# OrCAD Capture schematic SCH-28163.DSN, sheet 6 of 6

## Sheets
6 4. I/O Headers and Power Supply: size C
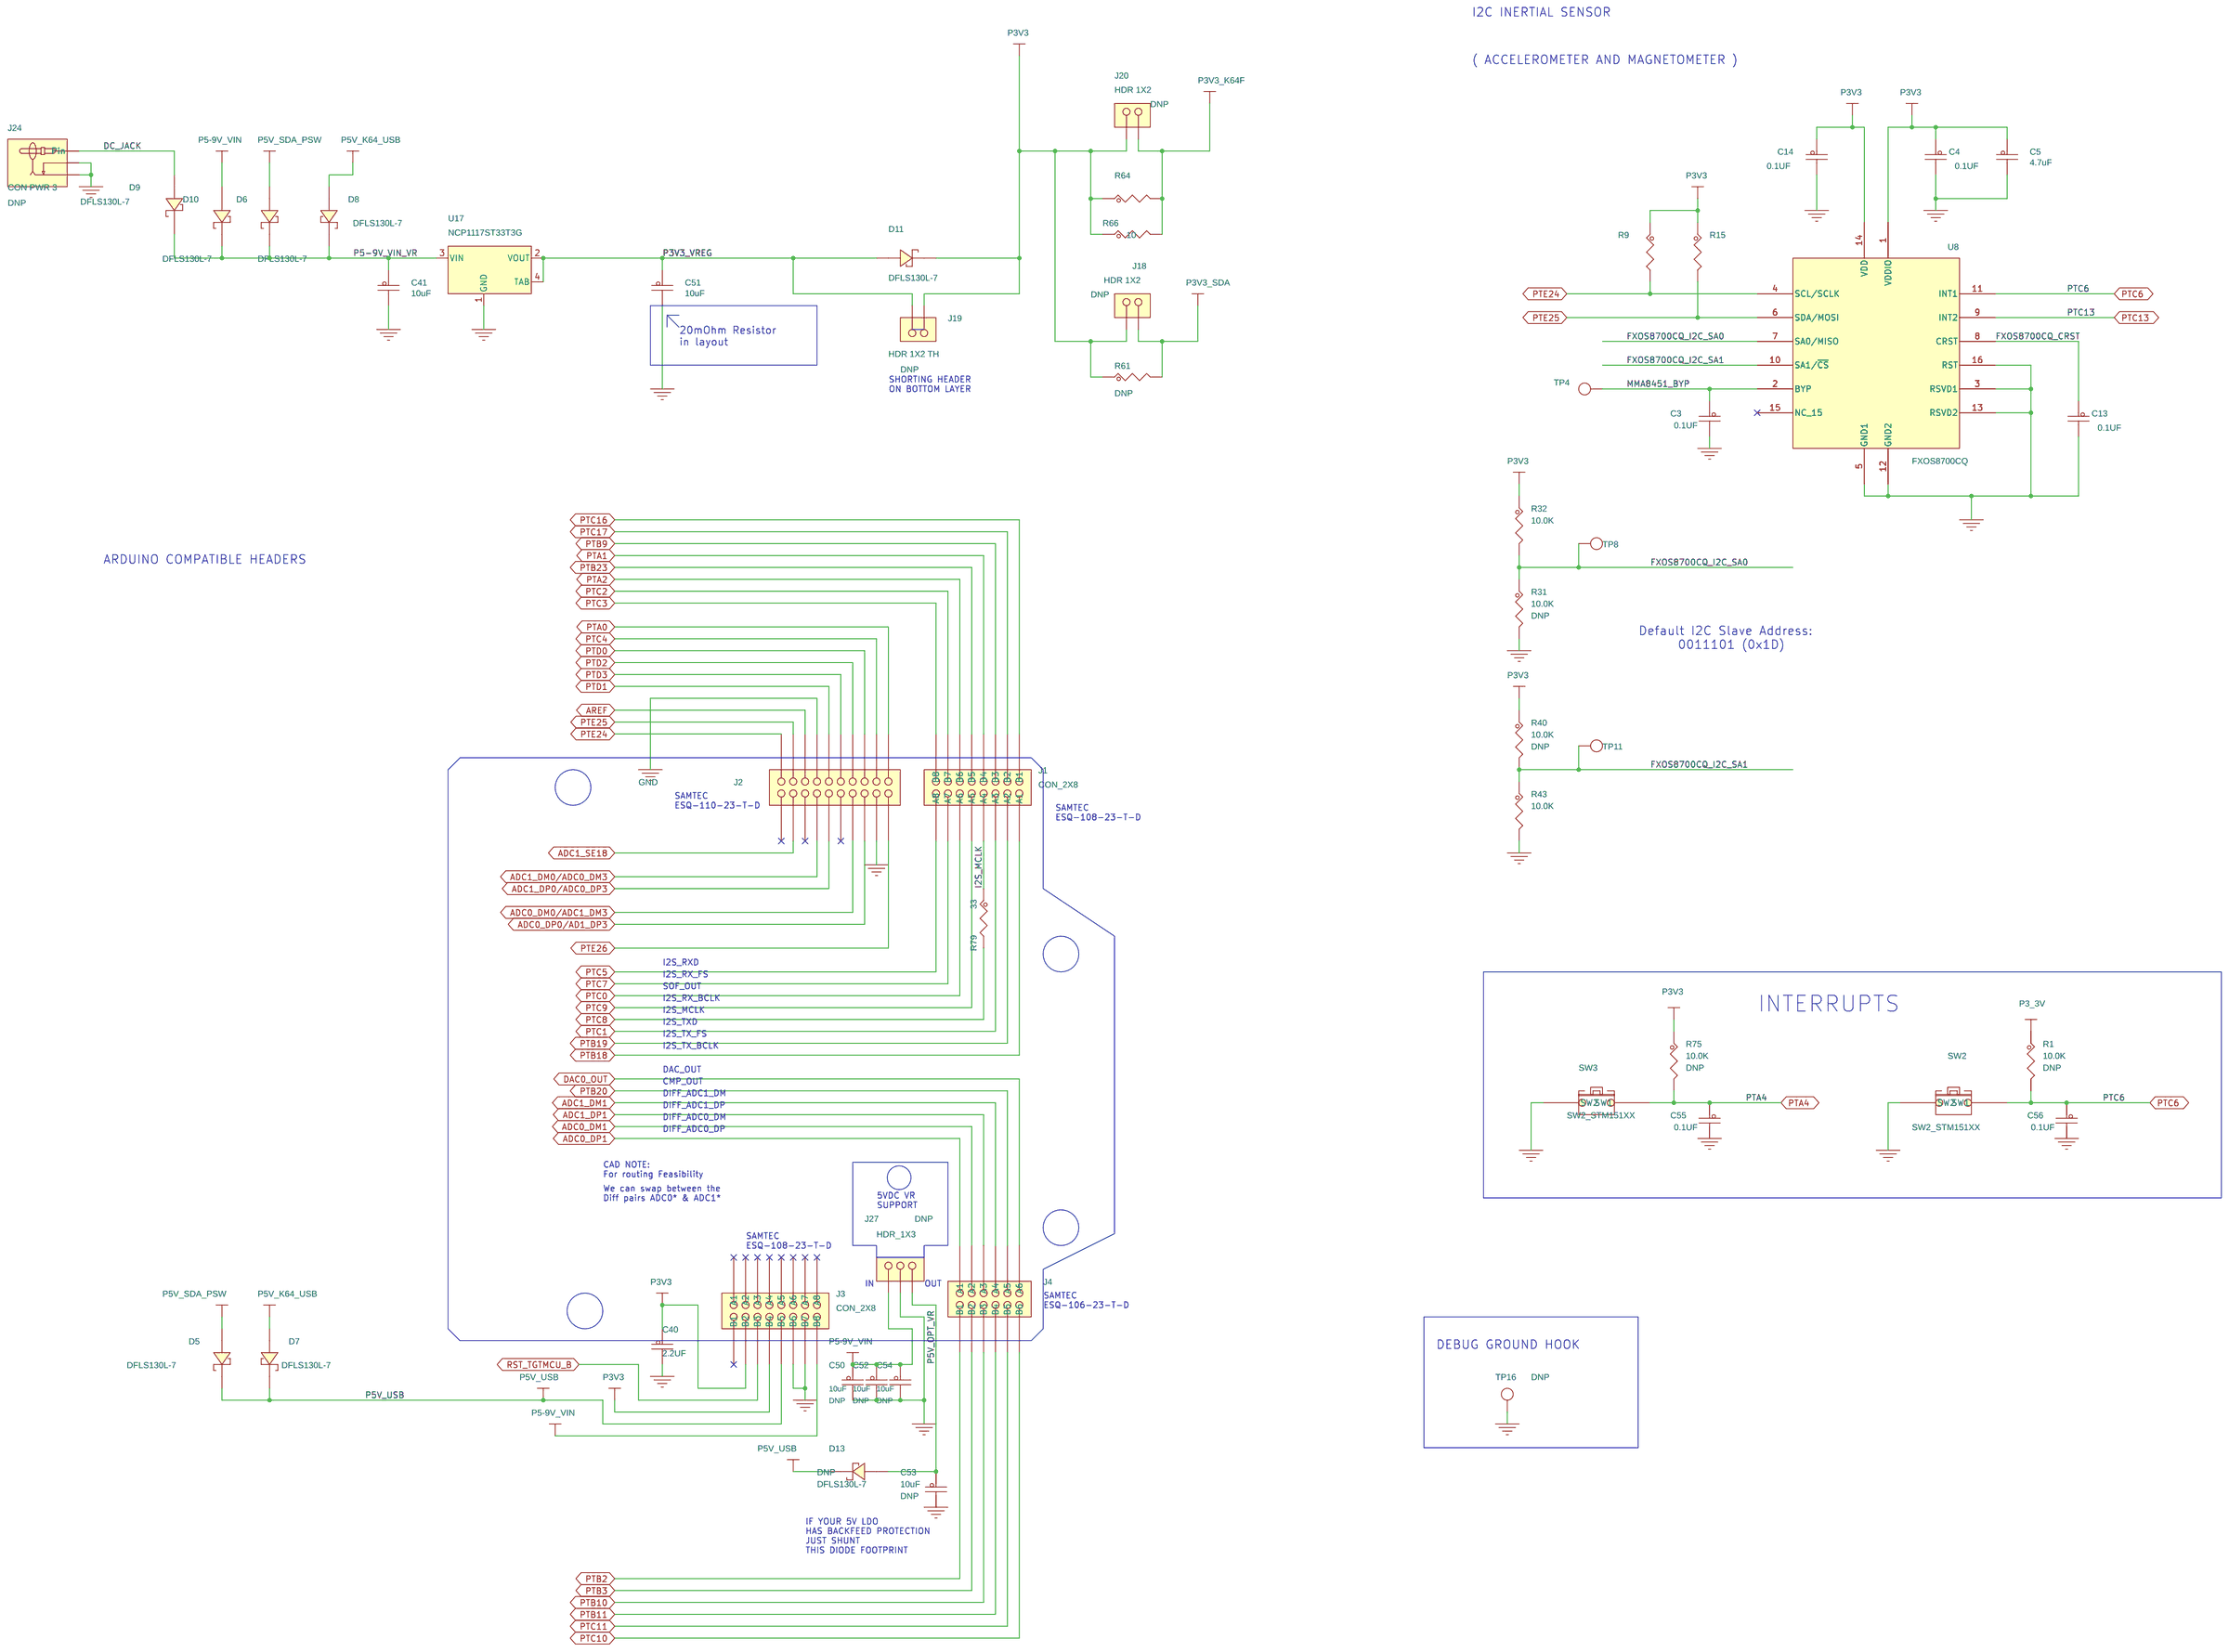
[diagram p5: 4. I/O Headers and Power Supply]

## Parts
C3  0.1UF  [CC0402_25]
C4  0.1UF  [CC0402_25]
C5  4.7uF  [CC0603_OV]
C13  0.1UF  [CC0402_25]
C14  0.1UF  [CC0402_25]
C40  2.2UF  [CC0603_OV]
C41  10uF  [CC0603_OV]
C50  10uF  [CC0603_OV]
C51  10uF  [CC0603_OV]
C52  10uF  [CC0603_OV]
C53  10uF  [CC0603_OV]
C54  10uF  [CC0603_OV]
C55  0.1UF  [CC0402_25]
C56  0.1UF  [CC0402_25]
D5  DFLS130L-7  [powerdi-123_3mmx2mm]
D6  DFLS130L-7  [powerdi-123_3mmx2mm]
D7  DFLS130L-7  [powerdi-123_3mmx2mm]
D8  DFLS130L-7  [powerdi-123_3mmx2mm]
D9  DFLS130L-7  [powerdi-123_3mmx2mm]
D10  DFLS130L-7  [powerdi-123_3mmx2mm]
D11  DFLS130L-7  [powerdi-123_3mmx2mm]
D13  DFLS130L-7  [powerdi-123_3mmx2mm]
J1  CON_2X8  [HDR208_ESQ_SKT]
J2  SKT_2x10  [hdr210_esq_skt]
J3  CON_2X8  [HDR208_ESQ_SKT]
J4  CON_2X6  [HDR206_ESQ_SKT]
J18  HDR 1X2  [hdr102]
J19  HDR 1X2 TH  [SH_HDR102_BOTTOM]
J20  HDR 1X2  [hdr102]
J24  CON PWR 3  [con_jack_pj1_022_th-ra]
J27  HDR_1X3  [HDR103]
R1  10.0K  [RC0402_25]
R9  4.7K  [RC0603_OV]
R15  4.7K  [RC0603_OV]
R31  10.0K  [RC0402_25]
R32  10.0K  [RC0402_25]
R40  10.0K  [RC0402_25]
R43  10.0K  [RC0402_25]
R61  0  [RC0402_25]
R64  0  [RC0402_25]
R66  10  [RC0603_OV]
R75  10.0K  [RC0402_25]
R79  33  [RC0402_25]
SW2  SW2_STM151XX  [sw2_4x3mm_sm]
SW3  SW2_STM151XX  [sw2_4x3mm_sm]
TP4  TPAD_030  [TPAD_030]
TP8  TPAD_030  [TPAD_030]
TP11  TPAD_030  [TPAD_030]
TP16  TEST POINT WHITE  [TEST_LOOP]
U8  FXOS8700CQ  [qfn5x3_0p5_3x3]
U17  NCP1117ST33T3G  [sot223]

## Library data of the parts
C3 C4 C13 C14 C55 C56 = CAP_NP: CAP CER 0.1UF 10V 10% X5R 0402; AGILE_PN: 150-75634; CAD_APPROVED: Yes; FPLIST: CC0402_25,CC0402_HD,0402_CC; HEIGHT: 0.64MM; MFG_NAME01: KEMET; MFG_PN01: C0402C104K8PAC; PRIORITY_PN: 021-00169; ROHS: Yes; SIGNAL_MODEL: DEFAULT_CAPACITOR_100000pF_2_1; Tolerance: 10%; VOLTAGE: 10V
C5 = CAP_NP: CAP CER 4.7uF 16V 10% X5R 0603; AGILE_PN: 150-78976; CAD_APPROVED: Yes; FPLIST: CC0603_OV,CC0603,0603_CC; HEIGHT: 0.9 MM; MFG_NAME01: TDK; MFG_PN01: C1608X5R1C475K; ROHS: Yes; SIGNAL_MODEL: DEFAULT_CAPACITOR_4.7e+06pF_2_1; Tolerance: 10%; VOLTAGE: 16V
C40 = CAP_NP: CAP CER 2.2UF 10V 10% X7R 0603; AGILE_PN: 150-78564; CAD_APPROVED: Yes; FPLIST: CC0603_OV,CC0603,0603_CC; HEIGHT: 1.25MM; MFG_NAME01: TAIYO YUDEN; MFG_PN01: LMK107B7225KA-T; ROHS: Yes; SIGNAL_MODEL: DEFAULT_CAPACITOR_2.2e+06pF_2_1; Tolerance: 10%; VOLTAGE: 10V
C41 = CAP_NP: CAP CER 10uF 16V 20% X5R 0603; AGILE_PN: 150-79092; CAD_APPROVED: Yes; FPLIST: CC0603_OV,CC0603,0603_CC; HEIGHT: 1mm; MFG_NAME01: TAIYO YUDEN; MFG_PN01: EMK107BBJ106MA-T; ROHS: Yes; SIGNAL_MODEL: DEFAULT_CAPACITOR_1e+07pF_2_1; Tolerance: 20%; VOLTAGE: 16V
C50 C52-C54 = CAP_NP: CAP CER 10UF 10V 20% X5R 0603; AGILE_PN: 150-78609; ASSY_OPT: DNP; CAD_APPROVED: Yes; FPLIST: CC0603_OV,CC0603,0603_CC; HEIGHT: 1.016MM; MFG_NAME01: TAIYO YUDEN; MFG_PN01: LMK107BJ106MALTD; ROHS: Yes; SIGNAL_MODEL: DEFAULT_CAPACITOR_1e+07pF_2_1; VOLTAGE: 10V
C51 = CAP_NP: CAP CER 10UF 10V 20% X5R 0603; AGILE_PN: 150-78609; CAD_APPROVED: Yes; FPLIST: CC0603_OV,CC0603,0603_CC; HEIGHT: 1.016MM; MFG_NAME01: TAIYO YUDEN; MFG_PN01: LMK107BJ106MALTD; ROHS: Yes; SIGNAL_MODEL: DEFAULT_CAPACITOR_1e+07pF_2_1; VOLTAGE: 10V
D5-D11 = DIODE_SCHTKY: DIODE SCH 1A 30V PowerDI123; AGILE_PN: 480-78285; CAD_APPROVED: Yes; HEIGHT: 1MM; MFG_NAME01: DIODES INC; ROHS: Yes
D13 = DIODE_SCHTKY: DIODE SCH 1A 30V PowerDI123; AGILE_PN: 480-78285; ASSY_OPT: DNP; CAD_APPROVED: Yes; HEIGHT: 1MM; MFG_NAME01: DIODES INC; ROHS: Yes
J1 J3 = CONN_HDR_8X2: CON 2X8 SKT TH 100MIL CTR 545H SN 190L; AGILE_PN: 210-80538; CAD_APPROVED: Yes; HEIGHT: 13.843MM; MFG_NAME01: samtec; MFG_PN01: ESQ-108-23-T-D; ROHS: Yes
J2 = CONN_HDR_10X2: CON 2X10 SKT TH 100MIL CTR 540H SN 190L; AGILE_PN: 210-80537; CAD_APPROVED: Yes; HEIGHT: 13.72MM; MFG_NAME01: SAMTEC; MFG_PN01: ESQ-110-23-T-D; ROHS: Yes
J4 = CONN_HDR_6X2: CON 2X6 SKT TH 100MIL CTR 540H SN 190L; AGILE_PN: 210-80536; CAD_APPROVED: Yes; HEIGHT: 13.72MM; MFG_NAME01: SAMTEC; MFG_PN01: ESQ-106-23-T-D; ROHS: Yes
J18 J20 = CONN_HDR_2X1: HDR 1X2 TH 100MIL SP 330H SN 115L; AGILE_PN: 210-76752; ASSY_OPT: DNP; CAD_APPROVED: Yes; HEIGHT: 8.58MM; MFG_NAME01: Samtec; MFG_PN01: TSW-102-23-T-S; ROHS: Yes
J19 = CONN_HDR_2X1: HDR 1X2 TH 100MIL SP 339H AU 98L; AGILE_PN: 210-75439; ASSY_OPT: DNP; CAD_APPROVED: YES; FPLIST: HDR102,SH_HDR102_BOTTOM; HEIGHT: 8.71 MM; MFG_NAME01: SAMTEC; MFG_PN01: TSW-102-07-G-S; PRIORITY_PN: 028-00556; ROHS: Yes
J24 = DC_POWER_JACK: CON 3 PWR JACK RA TH --- 201H AG 118L; AGILE_PN: 210-80316; ASSY_OPT: DNP; CAD_APPROVED: Yes; HEIGHT: 5.1MM; MFG_NAME01: CUI Inc; MFG_PN01: PJ1-022; ROHS: Yes
J27 = CONN_HDR_3X1: HDR 1X3 TH 100MIL SP 330H AU 98L; AGILE_PN: 210-75442; ASSY_OPT: DNP; CAD_APPROVED: Yes; HEIGHT: 8.38 MM; MFG_NAME01: SAMTEC; MFG_PN01: HTSW-103-07-S-S; PRIORITY_PN: 028-00700; ROHS: Yes
R1 R75 = RES: RES MF 10.0K 1/16W 1% AEC-Q200 0402; AGILE_PN: 470-75416; ASSY_OPT: DNP; CAD_APPROVED: Yes; FPLIST: RC0402_25,RC0402_HD,0402_CC; HEIGHT: 0.4MM; MFG_NAME01: VISHAY INTERTECHNOLOGY; MFG_PN01: CRCW040210K0FKED; PRIORITY_PN: 006-00552; ROHS: Yes; SIGNAL_MODEL: DEFAULT_RESISTOR_10000OHM_2_1; TOL: 1%; Tolerance: 1%
R9 R15 = RES: RES MF 4.7K 1/10W 5% 0603; AGILE_PN: 470-75414; CAD_APPROVED: Yes; FPLIST: RC0603_OV,RC0603,0603_CC; MFG_NAME01: VISHAY INTERTECHNOLOGY; MFG_PN01: CRCW06034K70JNEA; ROHS: Yes; SIGNAL_MODEL: DEFAULT_RESISTOR_4700OHM_2_1; Tolerance: 5%
R31 R40 = RES: RES MF 10.0K 1/16W 1% AEC-Q200 0402; AGILE_PN: 470-75416; ASSY_OPT: DNP; CAD_APPROVED: Yes; FPLIST: RC0402_25,RC0402_HD,0402_CC; MFG_NAME01: VISHAY INTERTECHNOLOGY; MFG_PN01: CRCW040210K0FKED; PRIORITY_PN: 006-00552; ROHS: Yes; SIGNAL_MODEL: DEFAULT_RESISTOR_10000OHM_2_1; Tolerance: 1%
R32 R43 = RES: RES MF 10.0K 1/16W 1% AEC-Q200 0402; AGILE_PN: 470-75416; CAD_APPROVED: Yes; FPLIST: RC0402_25,RC0402_HD,0402_CC; MFG_NAME01: VISHAY INTERTECHNOLOGY; MFG_PN01: CRCW040210K0FKED; PRIORITY_PN: 006-00552; ROHS: Yes; SIGNAL_MODEL: DEFAULT_RESISTOR_10000OHM_2_1; Tolerance: 1%
R61 = RES: RES MF ZERO OHM 1/16W 5% 0402; AGILE_PN: 470-75394; ASSY_OPT: DNP; CAD_APPROVED: Yes; FPLIST: RC0603_OV,RC0603,R603-X2,0603_CC; MFG_NAME01: ROHM; MFG_PN01: MCR01MZPJ000; PRIORITY_PN: 006-00559; ROHS: Yes; SIGNAL_MODEL: DEFAULT_RESISTOR_0.001OHM_2_1; Tolerance: 5%; VOLTAGE: 1/16W
R64 = RES: RES MF ZERO OHM 1/16W 5% 0402; AGILE_PN: 470-75394; CAD_APPROVED: Yes; FPLIST: RC0603_OV,RC0603,R603-X2,0603_CC; MFG_NAME01: ROHM; MFG_PN01: MCR01MZPJ000; PRIORITY_PN: 006-00559; ROHS: Yes; SIGNAL_MODEL: DEFAULT_RESISTOR_0.001OHM_2_1; Tolerance: 5%; VOLTAGE: 1/16W
R66 = RES: RES MF 10 OHM 1/10W 5% 0603; AGILE_PN: 470-75847; CAD_APPROVED: Yes; FPLIST: RC0603_OV,RC0603,0603_CC; MFG_NAME01: KOA SPEER; MFG_PN01: RK73B1JTTD100J; ROHS: Yes; SIGNAL_MODEL: DEFAULT_RESISTOR_10.000000OHM_2_1; Tolerance: 5%; VOLTAGE: 50V
R79 = RES: RES MF 33.0 OHM 1/16W 1% 0402; AGILE_PN: 470-75790; CAD_APPROVED: Yes; FPLIST: RC0402_25,RC0402_HD,RC0402_X2,0402_CC; MFG_NAME01: THYE MING TECH CO LTD; MFG_PN01: CR-02FL6---33R; ROHS: Yes; Tolerance: 1%
SW2 SW3 = SW2_STM151XX: SW SPST MOM NO TACT 12V 50MA SMT; AGILE_PN: 510-76958; CAD_APPROVED: Yes; HEIGHT: 2MM; MFG_NAME01: E SWITCH; MFG_PN01: TL1015BF160QG; ROHS: Yes
TP4 TP8 TP11 = TestLoop: TEST POINT PAD 30MIL DIA SMT, NO PART TO ORDER; AGILE_PN: 211-76642; CAD_APPROVED: Yes; HEIGHT: 0.1MM; MFG_NAME01: NOTACOMPONENT; MFG_PN01: NOTACOMPONENT; ROHS: Yes
TP16 = TestLoop: TEST POINT WHITE 40 MIL DRILL 180 MIL TH 109L; AGILE_PN: 210-75685; ASSY_OPT: DNP; CAD_APPROVED: Yes; HEIGHT: 4.8 MM; MFG_NAME01: COMPONENTS CORPORATION; MFG_PN01: TP-105-01-09; PRIORITY_PN: 028-00434; ROHS: Yes
U8 = FXOS8700CQ_QFN_16P: IC ACCELEROMETER AND MAGNETOMETER SENSOR 3-AXIS 2.5V QFN16; AGILE_PN: TMP-WF-16648; CAD_APPROVED: Yes; HEIGHT: 1.25MM; MFG_NAME01: Freescale Semiconductor; PRE_APN: 312-80418; ROHS: Yes; VOLTAGE: 2.5V
U17 = LD1117AS18: IC VREG LDO 1A 3.3V SOT223; AGILE_PN: 312-80039; CAD_APPROVED: Yes; HEIGHT: 1.8MM; MFG_NAME01: ON Semiconductor; ROHS: Yes

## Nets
GND: C3.2 C4.2 C5.2 C13.2 C14.2 C40.2 C41.2 C50.2 C51.2 C52.2 C53.2 C54.2 C55.2 C56.2 J2.3 J2.14 J3.12(B6) J3.14(B7) J24.2 J24.3 J27.2 R31.2 R43.2 SW2.2(SW2) SW3.2(SW2) TP16.1(Pin1) U8.3(RSVD1) U8.5(GND1) U8.12(GND2) U8.13(RSVD2) U8.16(RST) U17.1(GND) ; also on sheet 2 3 4 5
P3V3: C4.1 C5.1 C14.1 C40.1 D11.C J3.4(B2) J3.8(B4) J18.2 J19.1 J20.1 R1.1 R9.1 R15.1 R32.1 R40.1 R61.1 R64.1 R66.1 R75.1 U8.1(VDDIO) U8.14(VDD) ; also on sheet 2 3 4 5
P3V3_K64F: J20.2 R64.2 R66.2 ; also on sheet 2
P3V3_SDA: J18.1 R61.2 ; also on sheet 3
P3V3_VREG: C51.1 D11.A J19.2 U17.2(VOUT) U17.4(TAB)
P5V_K64_USB: D7.A D8.A ; also on sheet 2
P5V_OPT_VR: C53.1 D13.A J27.3
P5V_SDA_PSW: D5.A D6.A ; also on sheet 3
P5V_USB: D5.C D7.C D13.C J3.10(B5) ; also on sheet 2
ADC0_DM0/ADC1_DM3: J2.7 ; also on sheet 2
ADC0_DM1: J4.3(A2) ; also on sheet 2
ADC0_DP0/AD1_DP3: J2.5 ; also on sheet 2
ADC0_DP1: J4.1(A1) ; also on sheet 2
ADC1_DM0/ADC0_DM3: J2.13 ; also on sheet 2
ADC1_DM1: J4.7(A4) ; also on sheet 2
ADC1_DP0/ADC0_DP3: J2.11 ; also on sheet 2
ADC1_DP1: J4.5(A3) ; also on sheet 2
ADC1_SE18: J2.17 ; also on sheet 2
AREF: J2.16 ; also on sheet 2
DAC0_OUT: J4.11(A6) ; also on sheet 2
DC_JACK: D9.A J24.1(Pin)
FXOS8700CQ_CRST: C13.1 U8.8(CRST)
FXOS8700CQ_I2C_SA0: R31.1 R32.2 TP8.1(Pin1) U8.7(SA0/MISO)
FXOS8700CQ_I2C_SA1: R40.2 R43.1 TP11.1(Pin1) U8.10(SA1/~{CS})
I2S_MCLK: J1.7(A4) R79.1
MMA8451_BYP: C3.1 TP4.1(Pin1) U8.2(BYP)
P5-9V_VIN: C50.1 C52.1 C54.1 D10.A J3.16(B8) J27.1
P5-9V_VIN_VR: C41.1 D6.C D8.C D9.C D10.C U17.3(VIN)
PTA0: J2.2 ; also on sheet 2
PTA1: J1.8(B4) ; also on sheet 2
PTA2: J1.12(B6) ; also on sheet 2
PTA4: C55.1 R75.2 SW3.1(SW1) ; also on sheet 2
PTB2: J4.2(B1) ; also on sheet 2
PTB3: J4.4(B2) ; also on sheet 2
PTB9: J1.6(B3) ; also on sheet 2
PTB10: J4.6(B3) ; also on sheet 2
PTB11: J4.8(B4) ; also on sheet 2
PTB18: J1.1(A1) ; also on sheet 2
PTB19: J1.3(A2) ; also on sheet 2
PTB20: J4.9(A5) ; also on sheet 2
PTB23: J1.10(B5) ; also on sheet 2
PTC0: J1.11(A6) ; also on sheet 2
PTC1: J1.5(A3) ; also on sheet 2
PTC2: J1.14(B7) ; also on sheet 2
PTC3: J1.16(B8) ; also on sheet 2
PTC4: J2.4 ; also on sheet 2
PTC5: J1.15(A8) ; also on sheet 2
PTC6: C56.1 R1.2 SW2.1(SW1) U8.11(INT1) ; also on sheet 2
PTC7: J1.13(A7) ; also on sheet 2
PTC8: R79.2 ; also on sheet 2
PTC9: J1.9(A5) ; also on sheet 2
PTC10: J4.12(B6) ; also on sheet 2
PTC11: J4.10(B5) ; also on sheet 2
PTC13: U8.9(INT2) ; also on sheet 2
PTC16: J1.2(B1) ; also on sheet 2
PTC17: J1.4(B2) ; also on sheet 2
PTD0: J2.6 ; also on sheet 2
PTD1: J2.12 ; also on sheet 2
PTD2: J2.8 ; also on sheet 2
PTD3: J2.10 ; also on sheet 2
PTE24: J2.20 R9.2 U8.4(SCL/SCLK) ; also on sheet 2
PTE25: J2.18 R15.2 U8.6(SDA/MOSI) ; also on sheet 2
PTE26: J2.1 ; also on sheet 2
RST_TGTMCU_B: J3.6(B3) ; also on sheet 2 3 5

Not connected (* = marked no-connect by the designer): J2 9* 15* 19*; J3 1(A1)* 2(B1)* 3(A2)* 5(A3)* 7(A4)* 9(A5)* 11(A6)* 13(A7)* 15(A8)*; U8 15(NC)*

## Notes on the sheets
sheet 6
- I2C INERTIAL SENSOR
- ( ACCELEROMETER AND MAGNETOMETER )
- 20mOhm Resistor
  in layout
- SHORTING HEADER
  ON BOTTOM LAYER
- ARDUINO COMPATIBLE HEADERS
- Default I2C Slave Address:
        0011101 (0x1D)
- SAMTEC
  ESQ-110-23-T-D
- SAMTEC
  ESQ-108-23-T-D
- I2S_RXD
- I2S_RX_FS
- SOF_OUT
- I2S_RX_BCLK
- INTERRUPTS
- I2S_MCLK
- I2S_TXD
- I2S_TX_FS
- I2S_TX_BCLK
- DAC_OUT
- CMP_OUT
- DIFF_ADC1_DM
- DIFF_ADC1_DP
- DIFF_ADC0_DM
- DIFF_ADC0_DP
- CAD NOTE:
  For routing Feasibility
- We can swap between the
  Diff pairs ADC0* & ADC1*
- 5VDC VR
  SUPPORT
- SAMTEC
  ESQ-108-23-T-D
- IN
- OUT
- SAMTEC
  ESQ-106-23-T-D
- DEBUG GROUND HOOK
- IF YOUR 5V LDO
  HAS BACKFEED PROTECTION
  JUST SHUNT
  THIS DIODE FOOTPRINT
